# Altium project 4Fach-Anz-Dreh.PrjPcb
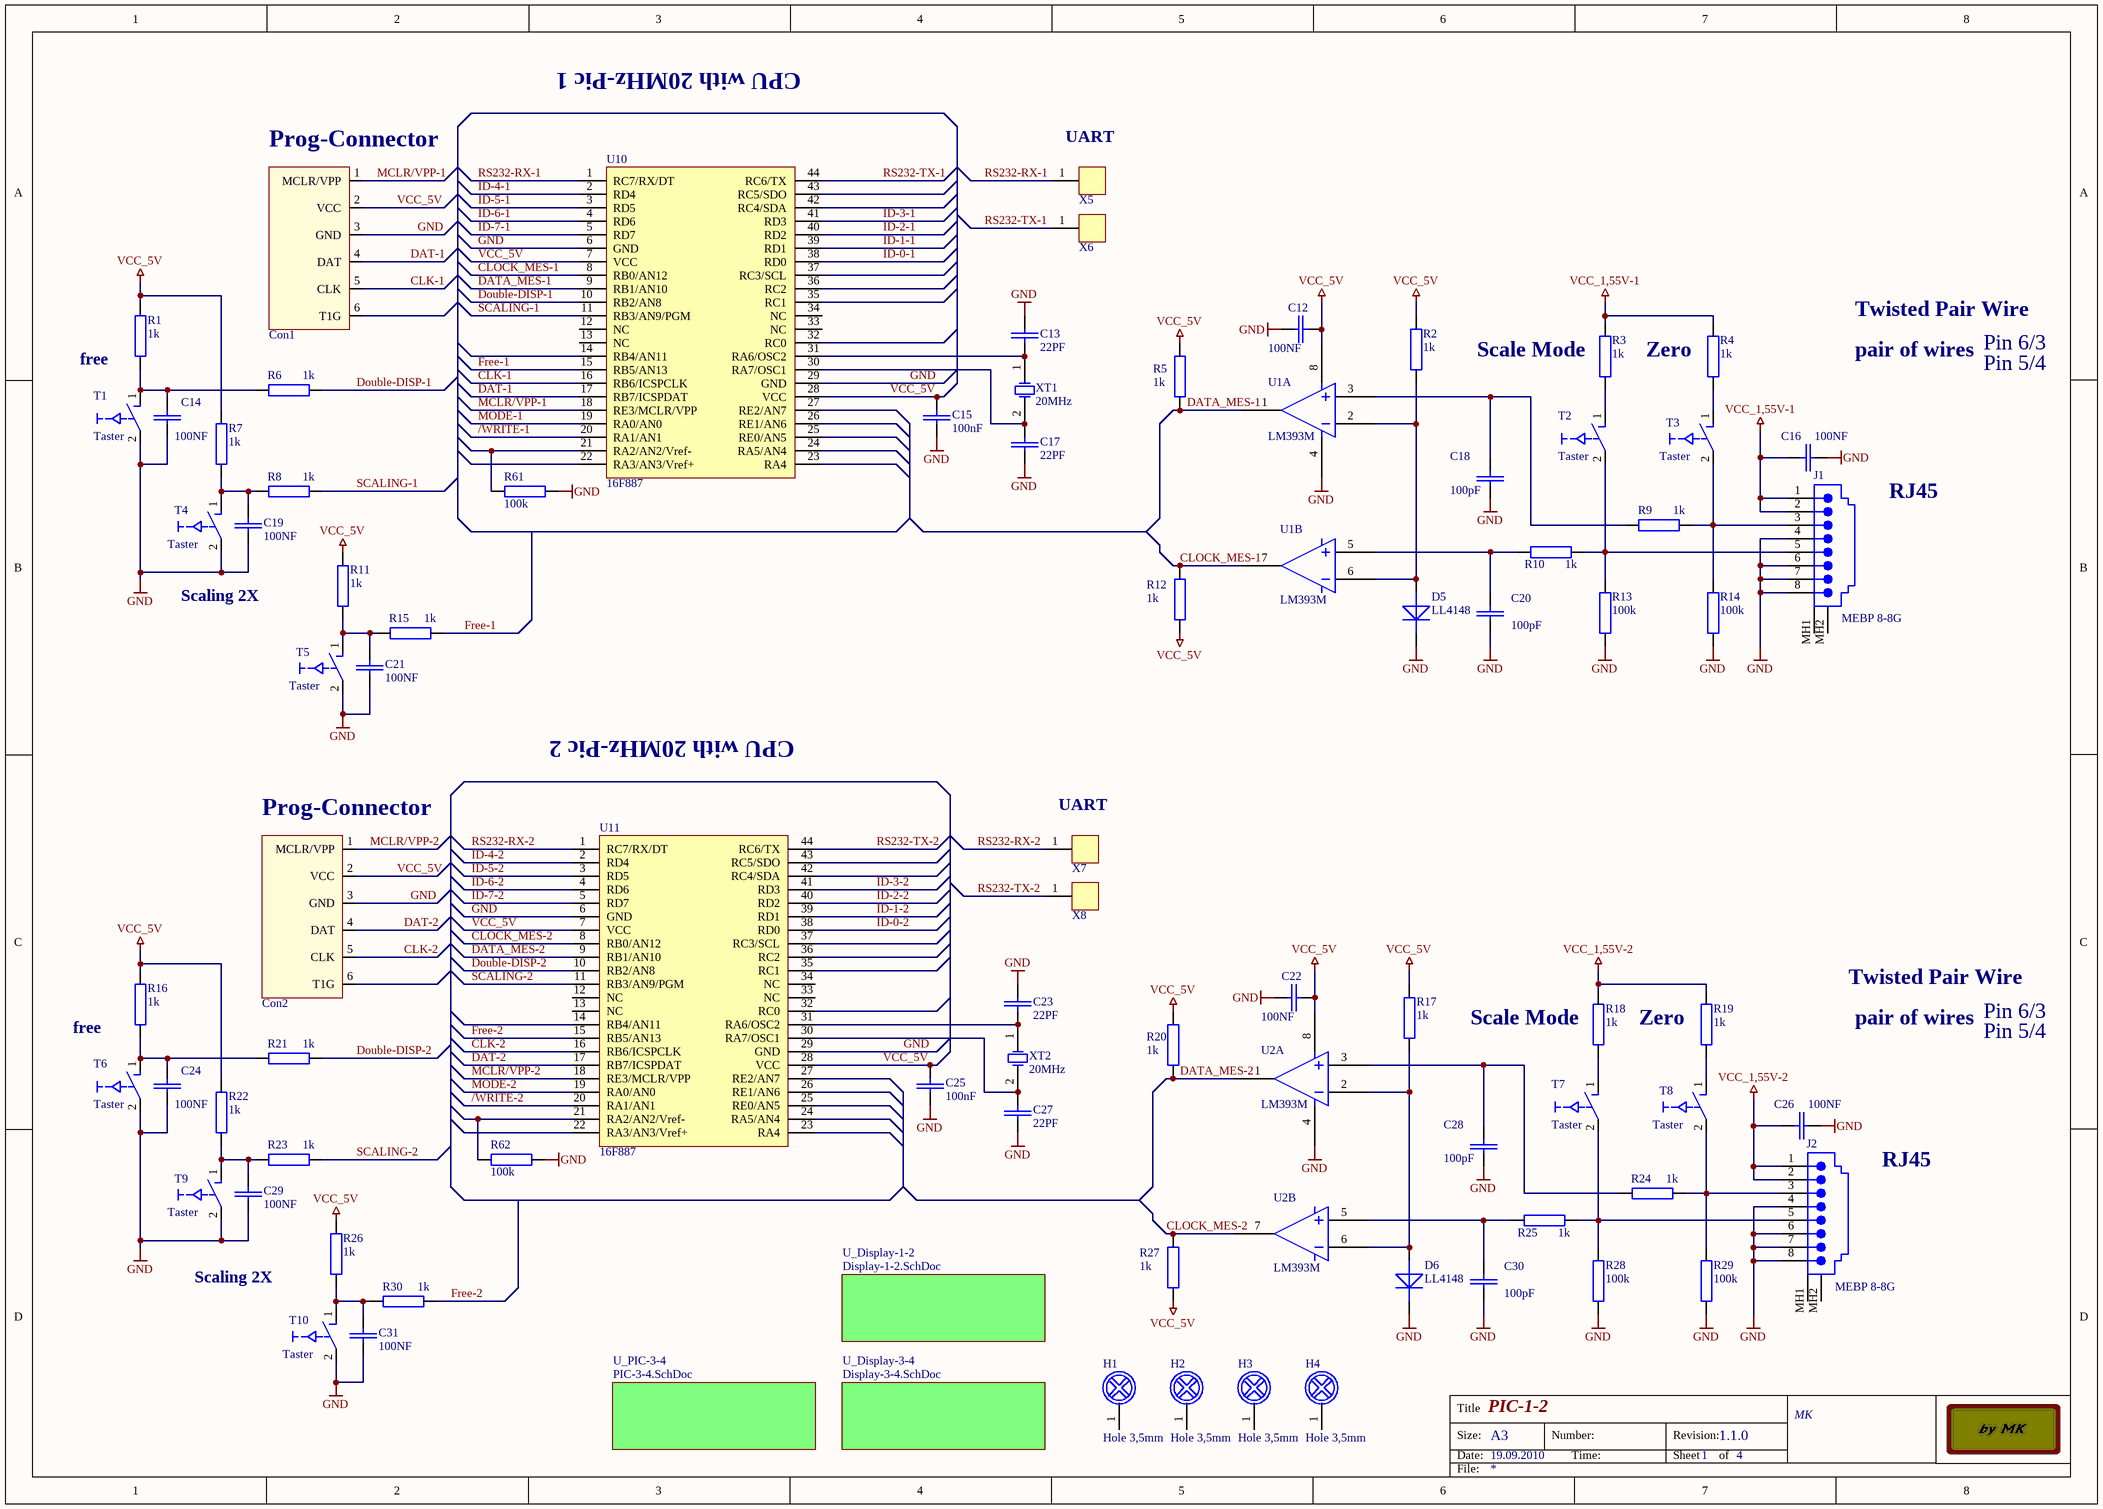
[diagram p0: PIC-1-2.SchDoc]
4 sheets, 204 parts. Net scope: global (net labels, ports and power ports of the same name join across sheets).
Board file: 4Fach-Anz-Dreh.PcbDoc
Sheets:
  PIC-1-2.SchDoc
    U_PIC-3-4 = PIC-3-4.SchDoc
    U_Display-1-2 = Display-1-2.SchDoc
    U_Display-3-4 = Display-3-4.SchDoc

## Sheet PIC-1-2.SchDoc: PIC-1-2
size A3; Organization: Altium Limited; Address1: MK; Revision: 1.1.0; SheetNumber: 1; SheetTotal: 4

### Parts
C12  100NF  [0805]
C13  22PF  [0805]
C14  100NF  [0805]
C15  100nF  [0805]
C16  100NF  [0805]
C17  22PF  [0805]
C18  100pF  [0805]
C19  100NF  [0805]
C20  100pF  [0805]
C21  100NF  [0805]
C22  100NF  [0805]
C23  22PF  [0805]
C24  100NF  [0805]
C25  100nF  [0805]
C26  100NF  [0805]
C27  22PF  [0805]
C28  100pF  [0805]
C29  100NF  [0805]
C30  100pF  [0805]
C31  100NF  [0805]
Con1  Con_6  [Con_6]  (value not drawn)
Con2  Con_6  [Con_6]  (value not drawn)
D5  LL4148  [MINIMELF]
D6  LL4148  [MINIMELF]
H1  Hole 3,5mm  [Hole 3,5mm]
H2  Hole 3,5mm  [Hole 3,5mm]
H3  Hole 3,5mm  [Hole 3,5mm]
H4  Hole 3,5mm  [Hole 3,5mm]
J1  MEBP 8-8G  [RJ45-JACK-MEBP 8-8G]
J2  MEBP 8-8G  [RJ45-JACK-MEBP 8-8G]
R1  1k  [0805]
R2  1k  [0805]
R3  1k  [0805]
R4  1k  [0805]
R5  1k  [0805]
R6  1k  [0805]
R7  1k  [0805]
R8  1k  [0805]
R9  1k  [0805]
R10  1k  [0805]
R11  1k  [0805]
R12  1k  [0805]
R13  100k  [0805]
R14  100k  [0805]
R15  1k  [0805]
R16  1k  [0805]
R17  1k  [0805]
R18  1k  [0805]
R19  1k  [0805]
R20  1k  [0805]
R21  1k  [0805]
R22  1k  [0805]
R23  1k  [0805]
R24  1k  [0805]
R25  1k  [0805]
R26  1k  [0805]
R27  1k  [0805]
R28  100k  [0805]
R29  100k  [0805]
R30  1k  [0805]
R61  100k  [0805]
R62  100k  [0805]
T1  Taster  [SIP2]
T2  Taster  [SIP2]
T3  Taster  [SIP2]
T4  Taster  [SIP2]
T5  Taster  [SIP2]
T6  Taster  [SIP2]
T7  Taster  [SIP2]
T8  Taster  [SIP2]
T9  Taster  [SIP2]
T10  Taster  [SIP2]
U1  LM393M  [SO-8]  (parts A,B of 2)
U2  LM393M  [SO-8]  (parts A,B of 2)
U10  16F887  [TQFP-44]
U11  16F887  [TQFP-44]
X5  Ground  [GND_PAD3]  (value not drawn)
X6  Ground  [GND_PAD3]  (value not drawn)
X7  Ground  [GND_PAD3]  (value not drawn)
X8  Ground  [GND_PAD3]  (value not drawn)
XT1  20MHz  [HC-49/U_ST]
XT2  20MHz  [HC-49/U_ST]

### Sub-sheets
U_Display-1-2 = Display-1-2.SchDoc: no entries
U_Display-3-4 = Display-3-4.SchDoc: no entries
U_PIC-3-4 = PIC-3-4.SchDoc: no entries

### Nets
GND: C12.2 C13.2 C14.2 C15.2 C16.2 C17.2 C18.2 C19.2 C20.2 C21.2 C22.2 C23.2 C24.2 C25.2 C26.2 C27.2 C28.2 C29.2 C30.2 C31.2 Con1.3(GND) Con2.3(GND) D5.K(CATHODE) D6.K(CATHODE) J1.4 J1.6 J1.7 J1.8 J2.4 J2.6 J2.7 J2.8 R13.2 R14.2 R28.2 R29.2 R61.2 R62.1 T1.2 T4.2 T5.2 T6.2 T9.2 T10.2 U1.4(V-) U2.4(V-) U10.6(GND) U10.29(GND) U11.6(GND) U11.29(GND)
VCC_1,55V-1: C16.1 J1.1 J1.2 R3.1 R4.1
VCC_1,55V-2: C26.1 J2.1 J2.2 R18.1 R19.1
VCC_5V: C12.1 C15.1 C22.1 C25.1 Con1.2(VCC) Con2.2(VCC) R1.1 R2.1 R5.2 R7.1 R11.1 R12.2 R16.1 R17.1 R20.2 R22.1 R26.1 R27.2 U1.8(V+) U2.8(V+) U10.7(VCC) U10.28(VCC) U11.7(VCC) U11.28(VCC)
/WRITE-1: U10.20(RA1/AN1)
/WRITE-2: U11.20(RA1/AN1)
CLK-1: Con1.5(CLK) U10.16(RB6/ICSPCLK)
CLK-2: Con2.5(CLK) U11.16(RB6/ICSPCLK)
CLOCK_MES-1: R12.1 U1.7 U10.8(RB0/AN12)
CLOCK_MES-2: R27.1 U2.7 U11.8(RB0/AN12)
DAT-1: Con1.4(DAT) U10.17(RB7/ICSPDAT)
DAT-2: Con2.4(DAT) U11.17(RB7/ICSPDAT)
DATA_MES-1: R5.1 U1.1 U10.9(RB1/AN10)
DATA_MES-2: R20.1 U2.1 U11.9(RB1/AN10)
Double-DISP-1: R6.2 U10.10(RB2/AN8)
Double-DISP-2: R21.2 U11.10(RB2/AN8)
Free-1: R15.2 U10.15(RB5/AN13)
Free-2: R30.2 U11.15(RB5/AN13)
ID-0-1: U10.38(RD0)
ID-0-2: U11.38(RD0)
ID-1-1: U10.39(RD1)
ID-1-2: U11.39(RD1)
ID-2-1: U10.40(RD2)
ID-2-2: U11.40(RD2)
ID-3-1: U10.41(RD3)
ID-3-2: U11.41(RD3)
ID-4-1: U10.2(RD4)
ID-4-2: U11.2(RD4)
ID-5-1: U10.3(RD5)
ID-5-2: U11.3(RD5)
ID-6-1: U10.4(RD6)
ID-6-2: U11.4(RD6)
ID-7-1: U10.5(RD7)
ID-7-2: U11.5(RD7)
MCLR/VPP-1: Con1.1(MCLR/VPP) U10.18(RE3/MCLR/VPP)
MCLR/VPP-2: Con2.1(MCLR/VPP) U11.18(RE3/MCLR/VPP)
MODE-1: U10.19(RA0/AN0)
MODE-2: U11.19(RA0/AN0)
RS232-RX-1: U10.1(RC7/RX/DT) X5.1
RS232-RX-2: U11.1(RC7/RX/DT) X7.1
RS232-TX-1: U10.44(RC6/TX) X6.1
RS232-TX-2: U11.44(RC6/TX) X8.1
SCALING-1: R8.2 U10.11(RB3/AN9/PGM)
SCALING-2: R23.2 U11.11(RB3/AN9/PGM)
NetC13_1: C13.1 U10.31(RA6/OSC2) XT1.1(OSC1)
NetC14_1: C14.1 R1.2 R6.1 T1.1
NetC17_1: C17.1 U10.30(RA7/OSC1) XT1.2(OSC2)
NetC18_1: C18.1 R9.1 U1.3
NetC19_1: C19.1 R7.2 R8.1 T4.1
NetC20_1: C20.1 R10.2 U1.5
NetC21_1: C21.1 R11.2 R15.1 T5.1
NetC23_1: C23.1 U11.31(RA6/OSC2) XT2.1(OSC1)
NetC24_1: C24.1 R16.2 R21.1 T6.1
NetC27_1: C27.1 U11.30(RA7/OSC1) XT2.2(OSC2)
NetC28_1: C28.1 R24.1 U2.3
NetC29_1: C29.1 R22.2 R23.1 T9.1
NetC30_1: C30.1 R25.2 U2.5
NetC31_1: C31.1 R26.2 R30.1 T10.1
NetD5_A: D5.A(ANODE) R2.2 U1.2 U1.6
NetD6_A: D6.A(ANODE) R17.2 U2.2 U2.6
NetJ1_3: J1.3 R9.2 R14.1 T3.2
NetJ1_5: J1.5 R10.1 R13.1 T2.2
NetJ2_3: J2.3 R24.2 R29.1 T8.2
NetJ2_5: J2.5 R25.1 R28.1 T7.2
NetR3_2: R3.2 T2.1
NetR4_2: R4.2 T3.1
NetR18_2: R18.2 T7.1
NetR19_2: R19.2 T8.1
NetR61_1: R61.1 U10.21(RA2/AN2/Vref-)
NetR62_2: R62.2 U11.21(RA2/AN2/Vref-)

Not connected (* = marked no-connect by the designer): Con1 6(T1G); Con2 6(T1G); H1 1; H2 1; H3 1; H4 1; J1 MH1(Shield) MH2(Shield); J2 MH1(Shield) MH2(Shield); U10 12(NC) 13(NC) 14(RB4/AN11) 22(RA3/AN3/Vref+) 23(RA4) 24(RA5/AN4) 25(RE0/AN5) 26(RE1/AN6) 27(RE2/AN7) 32(RC0) 33(NC) 34(NC) 35(RC1) 36(RC2) 37(RC3/SCL) 42(RC4/SDA) 43(RC5/SDO); U11 12(NC) 13(NC) 14(RB4/AN11) 22(RA3/AN3/Vref+) 23(RA4) 24(RA5/AN4) 25(RE0/AN5) 26(RE1/AN6) 27(RE2/AN7) 32(RC0) 33(NC) 34(NC) 35(RC1) 36(RC2) 37(RC3/SCL) 42(RC4/SDA) 43(RC5/SDO)

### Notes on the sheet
- CPU with 20MHz-Pic 1
- (near Con1) Prog-Connector
- (near X5) UART
- Twisted Pair Wire
- free
- (near R3) Scale Mode
- (near R4) Zero
- pair of wires
- Pin 6/3
- Pin 5/4
- RJ45
- Scaling 2X
- CPU with 20MHz-Pic 2
- (near Con2) Prog-Connector
- (near X7) UART
- (near R18) Scale Mode
- (near R19) Zero
- 19.09.2010

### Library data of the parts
C12 C14-C16 C19 C21 C22 C24-C26 C29 C31 = 100NF_0805: SMD Kondensator; Text Field1: 10%; Text Field3: 16V; Text Field5: 0603; Text Field6: Murata; Text Field7: RS;264-4422; Text Field8: 0,2132;SAP-NR.;220-7922
C13 C17 C23 C27 = 68PF_0805: SMD Kondensator; Text Field1: 5%; Text Field3: 50V; Text Field6: EPCOS;Farnell; Text Field7: 0,10;331-2884; Text Field8: 6507 3018
C18 C20 C28 C30 = 100PF_0805: Capacitor SMD; Part No.: 0157606; Tolerance: 10%; Class: passive; Voltage: 50V; Note: RoHS konf.; SAP No.: 6507 3077; Herst. Bezeichnung: MLCC NP0 0805 100pF 50V
D5 D6 = LL4148: Universal diode SMD; Manufacturer: VISHAY; Part No.: 9549986; Voltage: 75V; Current: 0,1A; SAP No.: 6506 2351; Class: passive; Note: RoHS konf.
J1 J2 = RJ45-JACK-MEBP 8-8G: Right Angle, Standard Profile, External Shield PCB Jack; Class: passive; Note: RoHS konf. / MEBP 8-8G; SubClass: Connector
R1-R12 R15-R27 R30 = 1k_0805: SMD Resistor; Part No.: 0234 1K; Power: 0,1W; Voltage: *V; SAP No.: 6507 4040; Tolerance: 1%; Class: passive; Note: RoHS Konf.
R13 R14 R28 R29 R61 R62 = 100K_0805: SMD Resistor; Part No.: 0234 100K; Power: 0,1W; Voltage: *V; SAP No.: 6507 4082; Tolerance: 1%; Class: passive; Note: RoHS Konf.
T1-T10 = TASTER_SCH
U1 U2 = LM393_SO-8: Dual Differential Comperator; Manufacturer: NATIONAL SEMICONDUCTOR; Part No.: 9487590; Class: active; Note: RoHS konf. /
U10 U11 = PIC-16F887: CPU
X5-X8 = GND_PAD3: Groundpad; Class: passive; SubClass: mechanic
XT1 XT2 = XTAL: Crystal Oscillator

## Sheet PIC-3-4.SchDoc: PIC-3-4
size A3; Organization: Altium Limited; Address1: MK; Revision: 1.1.0; SheetNumber: 2; SheetTotal: 4
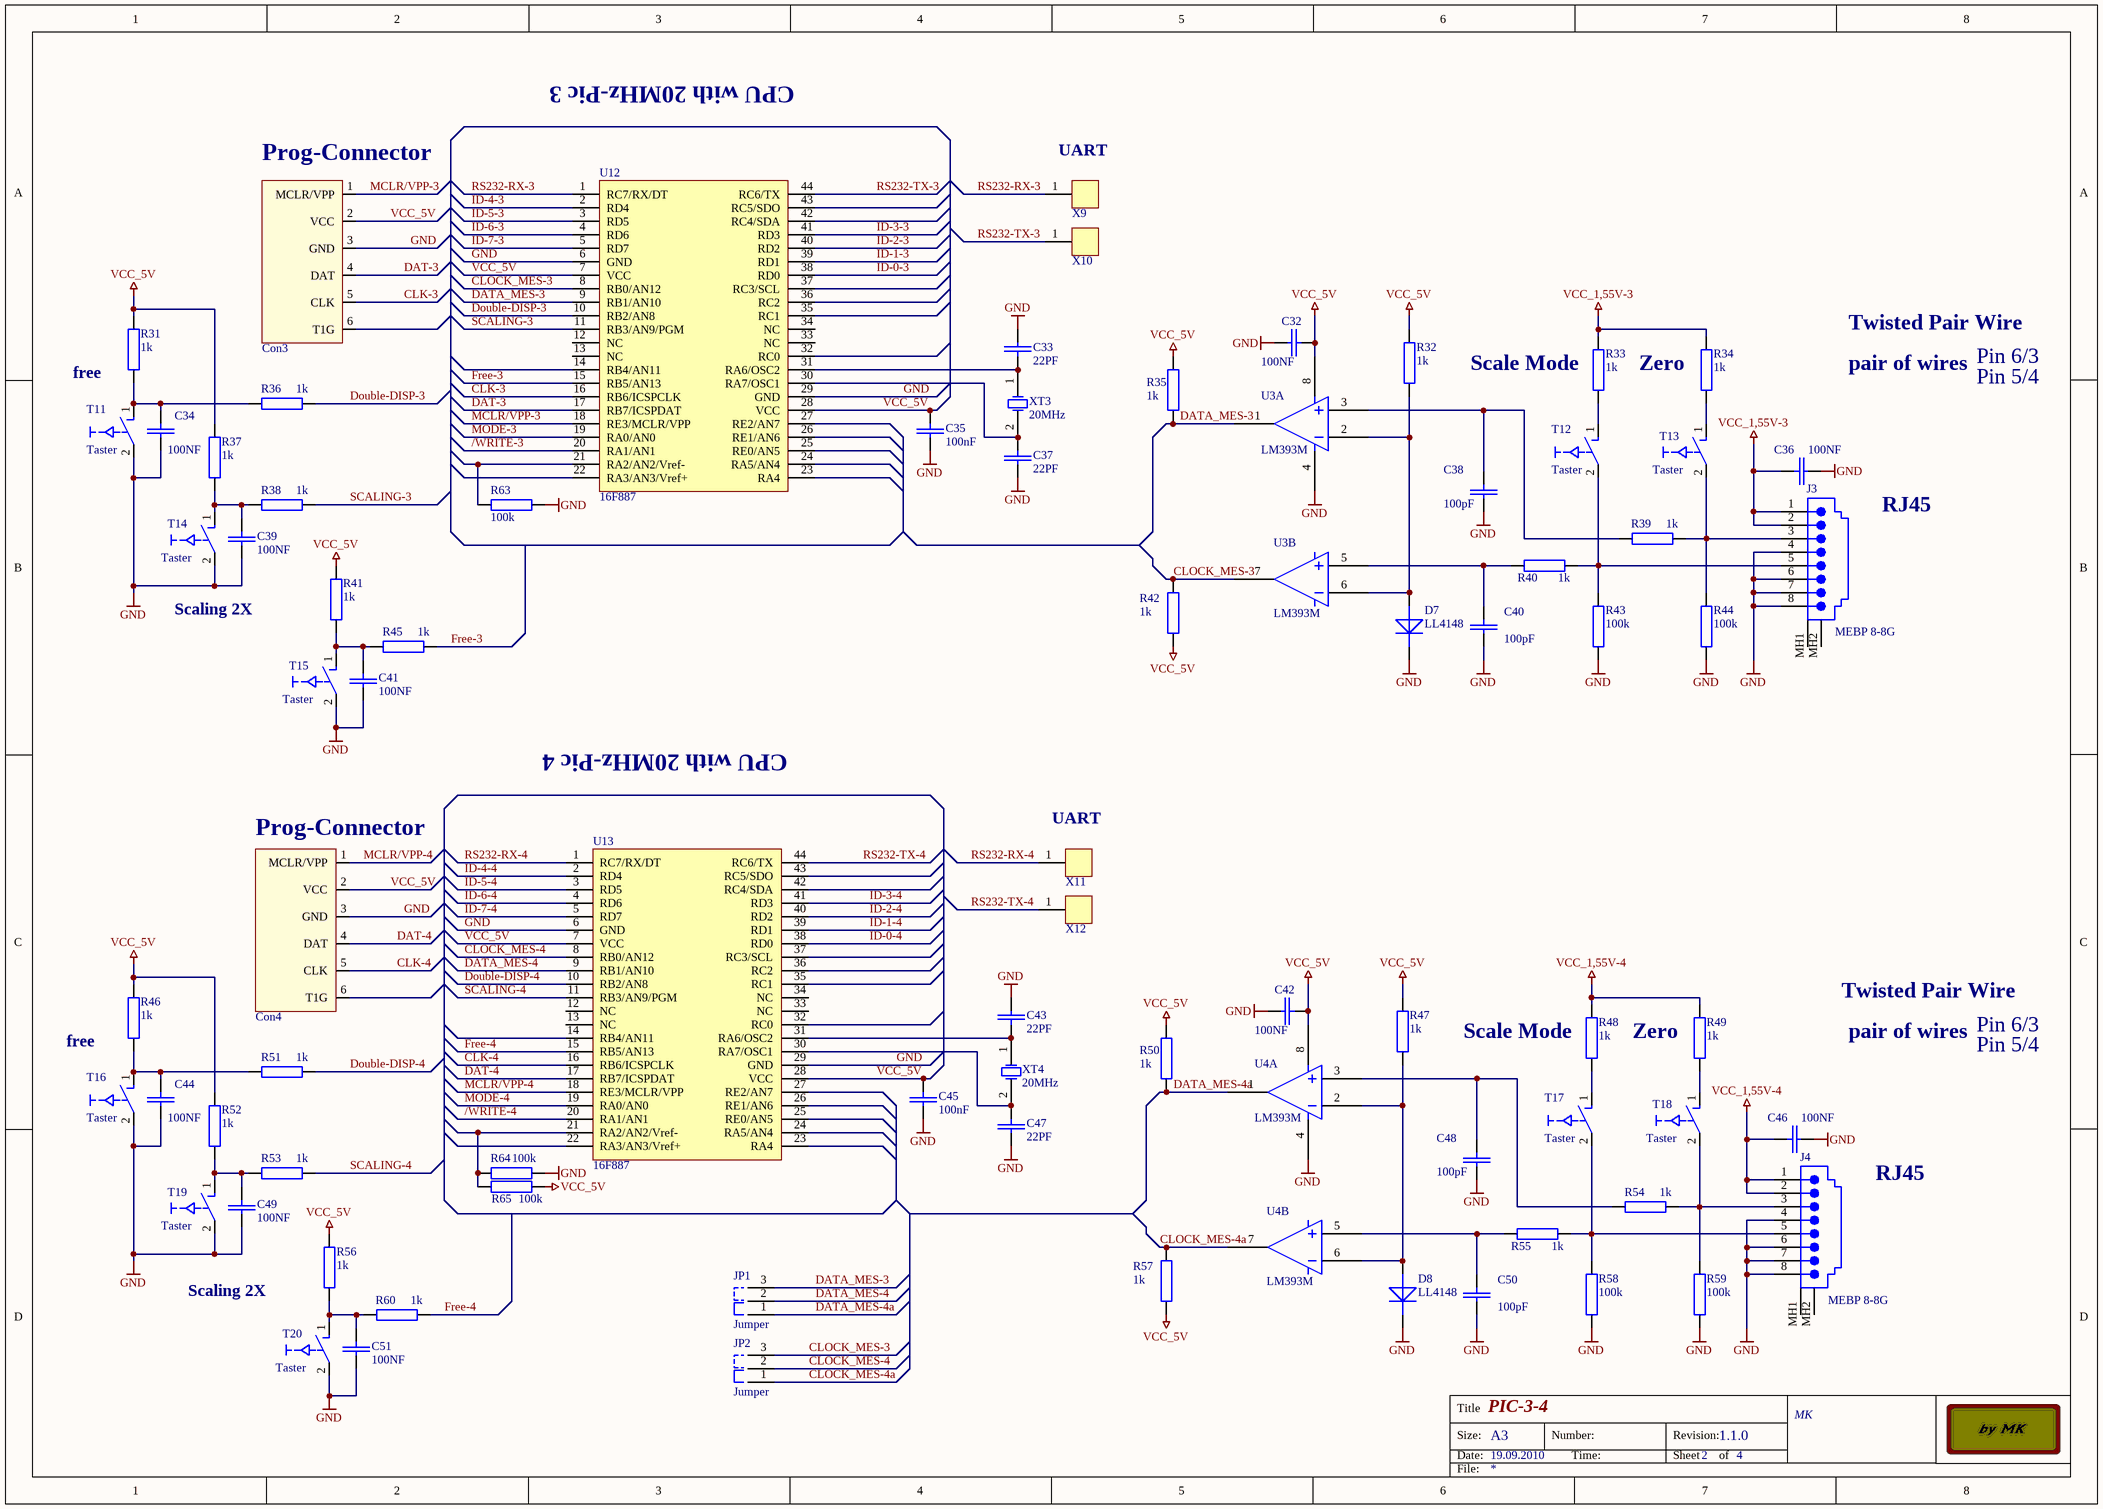
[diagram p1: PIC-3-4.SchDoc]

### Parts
C32  100NF  [0805]
C33  22PF  [0805]
C34  100NF  [0805]
C35  100nF  [0805]
C36  100NF  [0805]
C37  22PF  [0805]
C38  100pF  [0805]
C39  100NF  [0805]
C40  100pF  [0805]
C41  100NF  [0805]
C42  100NF  [0805]
C43  22PF  [0805]
C44  100NF  [0805]
C45  100nF  [0805]
C46  100NF  [0805]
C47  22PF  [0805]
C48  100pF  [0805]
C49  100NF  [0805]
C50  100pF  [0805]
C51  100NF  [0805]
Con3  Con_6  [Con_6]  (value not drawn)
Con4  Con_6  [Con_6]  (value not drawn)
D7  LL4148  [MINIMELF]
D8  LL4148  [MINIMELF]
J3  MEBP 8-8G  [RJ45-JACK-MEBP 8-8G]
J4  MEBP 8-8G  [RJ45-JACK-MEBP 8-8G]
JP1  Jumper  [SIP3]
JP2  Jumper  [SIP3]
R31  1k  [0805]
R32  1k  [0805]
R33  1k  [0805]
R34  1k  [0805]
R35  1k  [0805]
R36  1k  [0805]
R37  1k  [0805]
R38  1k  [0805]
R39  1k  [0805]
R40  1k  [0805]
R41  1k  [0805]
R42  1k  [0805]
R43  100k  [0805]
R44  100k  [0805]
R45  1k  [0805]
R46  1k  [0805]
R47  1k  [0805]
R48  1k  [0805]
R49  1k  [0805]
R50  1k  [0805]
R51  1k  [0805]
R52  1k  [0805]
R53  1k  [0805]
R54  1k  [0805]
R55  1k  [0805]
R56  1k  [0805]
R57  1k  [0805]
R58  100k  [0805]
R59  100k  [0805]
R60  1k  [0805]
R63  100k  [0805]
R64  100k  [0805]
R65  100k  [0805]
T11  Taster  [SIP2]
T12  Taster  [SIP2]
T13  Taster  [SIP2]
T14  Taster  [SIP2]
T15  Taster  [SIP2]
T16  Taster  [SIP2]
T17  Taster  [SIP2]
T18  Taster  [SIP2]
T19  Taster  [SIP2]
T20  Taster  [SIP2]
U3  LM393M  [SO-8]  (parts A,B of 2)
U4  LM393M  [SO-8]  (parts A,B of 2)
U12  16F887  [TQFP-44]
U13  16F887  [TQFP-44]
X9  Ground  [GND_PAD3]  (value not drawn)
X10  Ground  [GND_PAD3]  (value not drawn)
X11  Ground  [GND_PAD3]  (value not drawn)
X12  Ground  [GND_PAD3]  (value not drawn)
XT3  20MHz  [HC-49/U_ST]
XT4  20MHz  [HC-49/U_ST]

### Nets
GND: C32.2 C33.2 C34.2 C35.2 C36.2 C37.2 C38.2 C39.2 C40.2 C41.2 C42.2 C43.2 C44.2 C45.2 C46.2 C47.2 C48.2 C49.2 C50.2 C51.2 Con3.3(GND) Con4.3(GND) D7.K(CATHODE) D8.K(CATHODE) J3.4 J3.6 J3.7 J3.8 J4.4 J4.6 J4.7 J4.8 R43.2 R44.2 R58.2 R59.2 R63.1 R64.2 T11.2 T14.2 T15.2 T16.2 T19.2 T20.2 U3.4(V-) U4.4(V-) U12.6(GND) U12.29(GND) U13.6(GND) U13.29(GND)
VCC_1,55V-3: C36.1 J3.1 J3.2 R33.1 R34.1
VCC_1,55V-4: C46.1 J4.1 J4.2 R48.1 R49.1
VCC_5V: C32.1 C35.1 C42.1 C45.1 Con3.2(VCC) Con4.2(VCC) R31.1 R32.1 R35.2 R37.1 R41.1 R42.2 R46.1 R47.1 R50.2 R52.1 R56.1 R57.2 R65.2 U3.8(V+) U4.8(V+) U12.7(VCC) U12.28(VCC) U13.7(VCC) U13.28(VCC)
/WRITE-3: U12.20(RA1/AN1)
/WRITE-4: U13.20(RA1/AN1)
CLK-3: Con3.5(CLK) U12.16(RB6/ICSPCLK)
CLK-4: Con4.5(CLK) U13.16(RB6/ICSPCLK)
CLOCK_MES-3: JP2.3 R42.1 U3.7 U12.8(RB0/AN12)
CLOCK_MES-4: JP2.2 U13.8(RB0/AN12)
CLOCK_MES-4a: JP2.1 R57.1 U4.7
DAT-3: Con3.4(DAT) U12.17(RB7/ICSPDAT)
DAT-4: Con4.4(DAT) U13.17(RB7/ICSPDAT)
DATA_MES-3: JP1.3 R35.1 U3.1 U12.9(RB1/AN10)
DATA_MES-4: JP1.2 U13.9(RB1/AN10)
DATA_MES-4a: JP1.1 R50.1 U4.1
Double-DISP-3: R36.2 U12.10(RB2/AN8)
Double-DISP-4: R51.2 U13.10(RB2/AN8)
Free-3: R45.2 U12.15(RB5/AN13)
Free-4: R60.2 U13.15(RB5/AN13)
ID-0-3: U12.38(RD0)
ID-0-4: U13.38(RD0)
ID-1-3: U12.39(RD1)
ID-1-4: U13.39(RD1)
ID-2-3: U12.40(RD2)
ID-2-4: U13.40(RD2)
ID-3-3: U12.41(RD3)
ID-3-4: U13.41(RD3)
ID-4-3: U12.2(RD4)
ID-4-4: U13.2(RD4)
ID-5-3: U12.3(RD5)
ID-5-4: U13.3(RD5)
ID-6-3: U12.4(RD6)
ID-6-4: U13.4(RD6)
ID-7-3: U12.5(RD7)
ID-7-4: U13.5(RD7)
MCLR/VPP-3: Con3.1(MCLR/VPP) U12.18(RE3/MCLR/VPP)
MCLR/VPP-4: Con4.1(MCLR/VPP) U13.18(RE3/MCLR/VPP)
MODE-3: U12.19(RA0/AN0)
MODE-4: U13.19(RA0/AN0)
RS232-RX-3: U12.1(RC7/RX/DT) X9.1
RS232-RX-4: U13.1(RC7/RX/DT) X11.1
RS232-TX-3: U12.44(RC6/TX) X10.1
RS232-TX-4: U13.44(RC6/TX) X12.1
SCALING-3: R38.2 U12.11(RB3/AN9/PGM)
SCALING-4: R53.2 U13.11(RB3/AN9/PGM)
NetC33_1: C33.1 U12.31(RA6/OSC2) XT3.1(OSC1)
NetC34_1: C34.1 R31.2 R36.1 T11.1
NetC37_1: C37.1 U12.30(RA7/OSC1) XT3.2(OSC2)
NetC38_1: C38.1 R39.1 U3.3
NetC39_1: C39.1 R37.2 R38.1 T14.1
NetC40_1: C40.1 R40.2 U3.5
NetC41_1: C41.1 R41.2 R45.1 T15.1
NetC43_1: C43.1 U13.31(RA6/OSC2) XT4.1(OSC1)
NetC44_1: C44.1 R46.2 R51.1 T16.1
NetC47_1: C47.1 U13.30(RA7/OSC1) XT4.2(OSC2)
NetC48_1: C48.1 R54.1 U4.3
NetC49_1: C49.1 R52.2 R53.1 T19.1
NetC50_1: C50.1 R55.2 U4.5
NetC51_1: C51.1 R56.2 R60.1 T20.1
NetD7_A: D7.A(ANODE) R32.2 U3.2 U3.6
NetD8_A: D8.A(ANODE) R47.2 U4.2 U4.6
NetJ3_3: J3.3 R39.2 R44.1 T13.2
NetJ3_5: J3.5 R40.1 R43.1 T12.2
NetJ4_3: J4.3 R54.2 R59.1 T18.2
NetJ4_5: J4.5 R55.1 R58.1 T17.2
NetR33_2: R33.2 T12.1
NetR34_2: R34.2 T13.1
NetR48_2: R48.2 T17.1
NetR49_2: R49.2 T18.1
NetR63_2: R63.2 U12.21(RA2/AN2/Vref-)
NetR64_1: R64.1 R65.1 U13.21(RA2/AN2/Vref-)

Not connected (* = marked no-connect by the designer): Con3 6(T1G); Con4 6(T1G); J3 MH1(Shield) MH2(Shield); J4 MH1(Shield) MH2(Shield); U12 12(NC) 13(NC) 14(RB4/AN11) 22(RA3/AN3/Vref+) 23(RA4) 24(RA5/AN4) 25(RE0/AN5) 26(RE1/AN6) 27(RE2/AN7) 32(RC0) 33(NC) 34(NC) 35(RC1) 36(RC2) 37(RC3/SCL) 42(RC4/SDA) 43(RC5/SDO); U13 12(NC) 13(NC) 14(RB4/AN11) 22(RA3/AN3/Vref+) 23(RA4) 24(RA5/AN4) 25(RE0/AN5) 26(RE1/AN6) 27(RE2/AN7) 32(RC0) 33(NC) 34(NC) 35(RC1) 36(RC2) 37(RC3/SCL) 42(RC4/SDA) 43(RC5/SDO)

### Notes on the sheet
- CPU with 20MHz-Pic 3
- (near Con3) Prog-Connector
- (near X9) UART
- free
- (near R33) Scale Mode
- (near R34) Zero
- Twisted Pair Wire
- pair of wires
- Pin 6/3
- Pin 5/4
- RJ45
- Scaling 2X
- CPU with 20MHz-Pic 4
- (near Con4) Prog-Connector
- (near X11) UART
- (near R48) Scale Mode
- (near R49) Zero
- 19.09.2010

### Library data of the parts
C32 C34-C36 C39 C41 C42 C44-C46 C49 C51 = 100NF_0805: as C12 on sheet PIC-1-2
C33 C37 C43 C47 = 68PF_0805: as C13 on sheet PIC-1-2
C38 C40 C48 C50 = 100PF_0805: as C18 on sheet PIC-1-2
D7 D8 = LL4148: as D5 on sheet PIC-1-2
J3 J4 = RJ45-JACK-MEBP 8-8G: as J1 on sheet PIC-1-2
JP1 JP2 = JUMPER3: Lötaugen; Class: passive; SubClass: Connector
R31-R42 R45-R57 R60 = 1k_0805: as R1 on sheet PIC-1-2
R43 R44 R58 R59 R63-R65 = 100K_0805: as R13 on sheet PIC-1-2
T11-T20 = TASTER_SCH
U3 U4 = LM393_SO-8: as U1 on sheet PIC-1-2
U12 U13 = PIC-16F887: CPU
X9-X12 = GND_PAD3: as X5 on sheet PIC-1-2
XT3 XT4 = XTAL: Crystal Oscillator

## Sheet Display-1-2.SchDoc: Display-1-2
size A3; Organization: Altium Limited; Address1: MK; Revision: 1.1.0; SheetNumber: 3; SheetTotal: 4
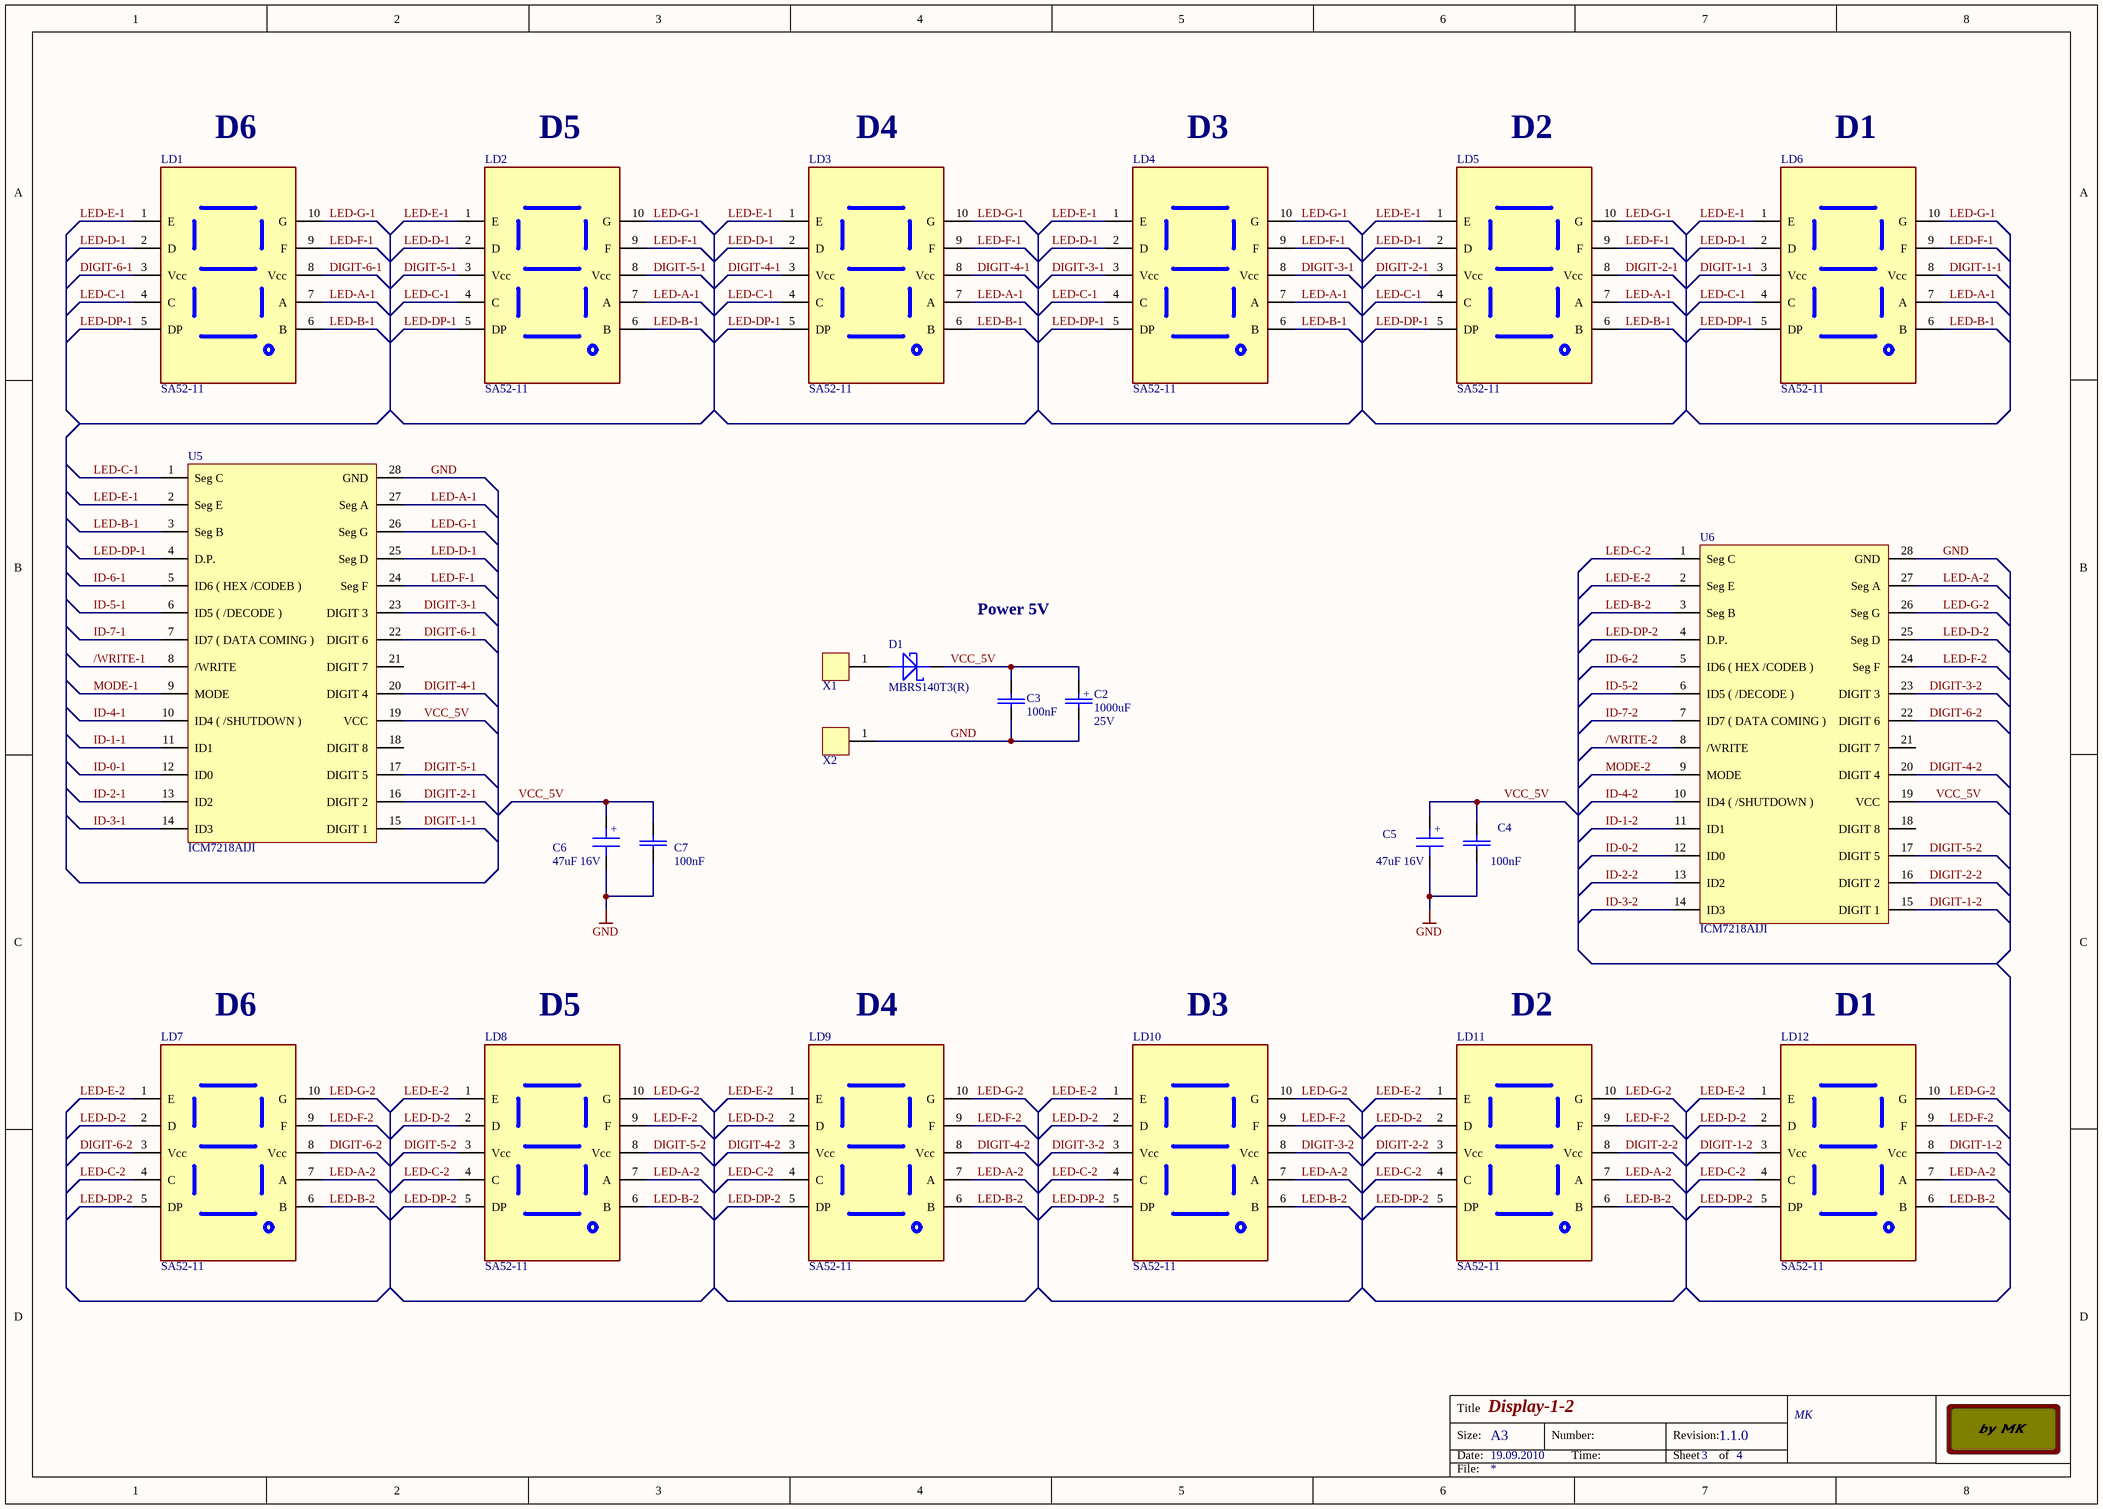
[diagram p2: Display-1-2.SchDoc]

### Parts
C2  1000uF  TechSpannung: 25V  [ELK_RM050_10x12.5]
C3  100nF  [0805]
C4  100nF  [0805]
C5  47uF 16V  [Bauform_C]
C6  47uF 16V  [Bauform_C]
C7  100nF  [0805]
D1  MBRS140T3(R)  [SMB]
LD1  SA52-11  [SA52-11]
LD2  SA52-11  [SA52-11]
LD3  SA52-11  [SA52-11]
LD4  SA52-11  [SA52-11]
LD5  SA52-11  [SA52-11]
LD6  SA52-11  [SA52-11]
LD7  SA52-11  [SA52-11]
LD8  SA52-11  [SA52-11]
LD9  SA52-11  [SA52-11]
LD10  SA52-11  [SA52-11]
LD11  SA52-11  [SA52-11]
LD12  SA52-11  [SA52-11]
U5  ICM7218AIJI  [ICM7218AIJM]
U6  ICM7218AIJI  [ICM7218AIJM]
X1  Ground  [GND_PAD3]  (value not drawn)
X2  Ground  [GND_PAD3]  (value not drawn)

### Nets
GND: C2.2 C3.2 C4.2 C5.2 C6.2 C7.2 U5.28(GND) U6.28(GND) X2.1
VCC_5V: C2.1 C3.1 C4.1 C5.1 C6.1 C7.1 D1.K(CATHODE) U5.19(VCC) U6.19(VCC)
/WRITE-1: U5.8(/WRITE)
/WRITE-2: U6.8(/WRITE)
DIGIT-1-1: LD6.3(Vcc) LD6.8(Vcc) U5.15(DIGIT_1)
DIGIT-1-2: LD12.3(Vcc) LD12.8(Vcc) U6.15(DIGIT_1)
DIGIT-2-1: LD5.3(Vcc) LD5.8(Vcc) U5.16(DIGIT_2)
DIGIT-2-2: LD11.3(Vcc) LD11.8(Vcc) U6.16(DIGIT_2)
DIGIT-3-1: LD4.3(Vcc) LD4.8(Vcc) U5.23(DIGIT_3)
DIGIT-3-2: LD10.3(Vcc) LD10.8(Vcc) U6.23(DIGIT_3)
DIGIT-4-1: LD3.3(Vcc) LD3.8(Vcc) U5.20(DIGIT_4)
DIGIT-4-2: LD9.3(Vcc) LD9.8(Vcc) U6.20(DIGIT_4)
DIGIT-5-1: LD2.3(Vcc) LD2.8(Vcc) U5.17(DIGIT_5)
DIGIT-5-2: LD8.3(Vcc) LD8.8(Vcc) U6.17(DIGIT_5)
DIGIT-6-1: LD1.3(Vcc) LD1.8(Vcc) U5.22(DIGIT_6)
DIGIT-6-2: LD7.3(Vcc) LD7.8(Vcc) U6.22(DIGIT_6)
ID-0-1: U5.12(ID0)
ID-0-2: U6.12(ID0)
ID-1-1: U5.11(ID1)
ID-1-2: U6.11(ID1)
ID-2-1: U5.13(ID2)
ID-2-2: U6.13(ID2)
ID-3-1: U5.14(ID3)
ID-3-2: U6.14(ID3)
ID-4-1: U5.10(ID4_(_/SHUTDOWN_))
ID-4-2: U6.10(ID4_(_/SHUTDOWN_))
ID-5-1: U5.6(ID5_(_/DECODE_))
ID-5-2: U6.6(ID5_(_/DECODE_))
ID-6-1: U5.5(ID6_(_HEX_/CODEB_))
ID-6-2: U6.5(ID6_(_HEX_/CODEB_))
ID-7-1: U5.7(ID7_(_DATA_COMING_))
ID-7-2: U6.7(ID7_(_DATA_COMING_))
LED-A-1: LD1.7(A) LD2.7(A) LD3.7(A) LD4.7(A) LD5.7(A) LD6.7(A) U5.27(Seg_A)
LED-A-2: LD7.7(A) LD8.7(A) LD9.7(A) LD10.7(A) LD11.7(A) LD12.7(A) U6.27(Seg_A)
LED-B-1: LD1.6(B) LD2.6(B) LD3.6(B) LD4.6(B) LD5.6(B) LD6.6(B) U5.3(Seg_B)
LED-B-2: LD7.6(B) LD8.6(B) LD9.6(B) LD10.6(B) LD11.6(B) LD12.6(B) U6.3(Seg_B)
LED-C-1: LD1.4(C) LD2.4(C) LD3.4(C) LD4.4(C) LD5.4(C) LD6.4(C) U5.1(Seg_C)
LED-C-2: LD7.4(C) LD8.4(C) LD9.4(C) LD10.4(C) LD11.4(C) LD12.4(C) U6.1(Seg_C)
LED-D-1: LD1.2(D) LD2.2(D) LD3.2(D) LD4.2(D) LD5.2(D) LD6.2(D) U5.25(Seg_D)
LED-D-2: LD7.2(D) LD8.2(D) LD9.2(D) LD10.2(D) LD11.2(D) LD12.2(D) U6.25(Seg_D)
LED-DP-1: LD1.5(DP) LD2.5(DP) LD3.5(DP) LD4.5(DP) LD5.5(DP) LD6.5(DP) U5.4(D.P.)
LED-DP-2: LD7.5(DP) LD8.5(DP) LD9.5(DP) LD10.5(DP) LD11.5(DP) LD12.5(DP) U6.4(D.P.)
LED-E-1: LD1.1(E) LD2.1(E) LD3.1(E) LD4.1(E) LD5.1(E) LD6.1(E) U5.2(Seg_E)
LED-E-2: LD7.1(E) LD8.1(E) LD9.1(E) LD10.1(E) LD11.1(E) LD12.1(E) U6.2(Seg_E)
LED-F-1: LD1.9(F) LD2.9(F) LD3.9(F) LD4.9(F) LD5.9(F) LD6.9(F) U5.24(Seg_F)
LED-F-2: LD7.9(F) LD8.9(F) LD9.9(F) LD10.9(F) LD11.9(F) LD12.9(F) U6.24(Seg_F)
LED-G-1: LD1.10(G) LD2.10(G) LD3.10(G) LD4.10(G) LD5.10(G) LD6.10(G) U5.26(Seg_G)
LED-G-2: LD7.10(G) LD8.10(G) LD9.10(G) LD10.10(G) LD11.10(G) LD12.10(G) U6.26(Seg_G)
MODE-1: U5.9(MODE)
MODE-2: U6.9(MODE)
NetD1_A: D1.A(ANODE) X1.1

Not connected (* = marked no-connect by the designer): U5 18(DIGIT_8) 21(DIGIT_7); U6 18(DIGIT_8) 21(DIGIT_7)

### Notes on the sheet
- D6
- D5
- D4
- D3
- D2
- D1
- Power 5V
- 19.09.2010

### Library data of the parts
C2 = 1000UF_RM5_25V: Capacitor Aluminum Electrolytic, 1000UF, 25V, 20%, 105°C, Low impedance; Manufacturer: RUBYCON; Part No.: 1144624; Class: passive; Note: RoHS konf. / High Ripple Current; Herst. Bezeichnung: 25YXF1000M12.5X20
C3 C4 C7 = 100NF_0805: as C12 on sheet PIC-1-2
C5 C6 = TR3 Tantal 47uF 16V: Tantal 47uF 16V
D1 = MBRS140T3(R)_SMB: Schottkydiode _SMD; Manufacturer: ON; Part No.: MBRS 140 SMD;MBRS140T3G; 9557237; Voltage: 40V; Current: 1A; Class: passive; Note: RoHS konf.; Herst. Bezeichnung: MBRS140T3G
LD1-LD12 = SA52-11: 7-Segment-Anzeige 13mm
X1 X2 = GND_PAD3: as X5 on sheet PIC-1-2

## Sheet Display-3-4.SchDoc: Display-3-4
size A3; Organization: Altium Limited; Address1: MK; Revision: 1.1.0; SheetNumber: 4; SheetTotal: 4
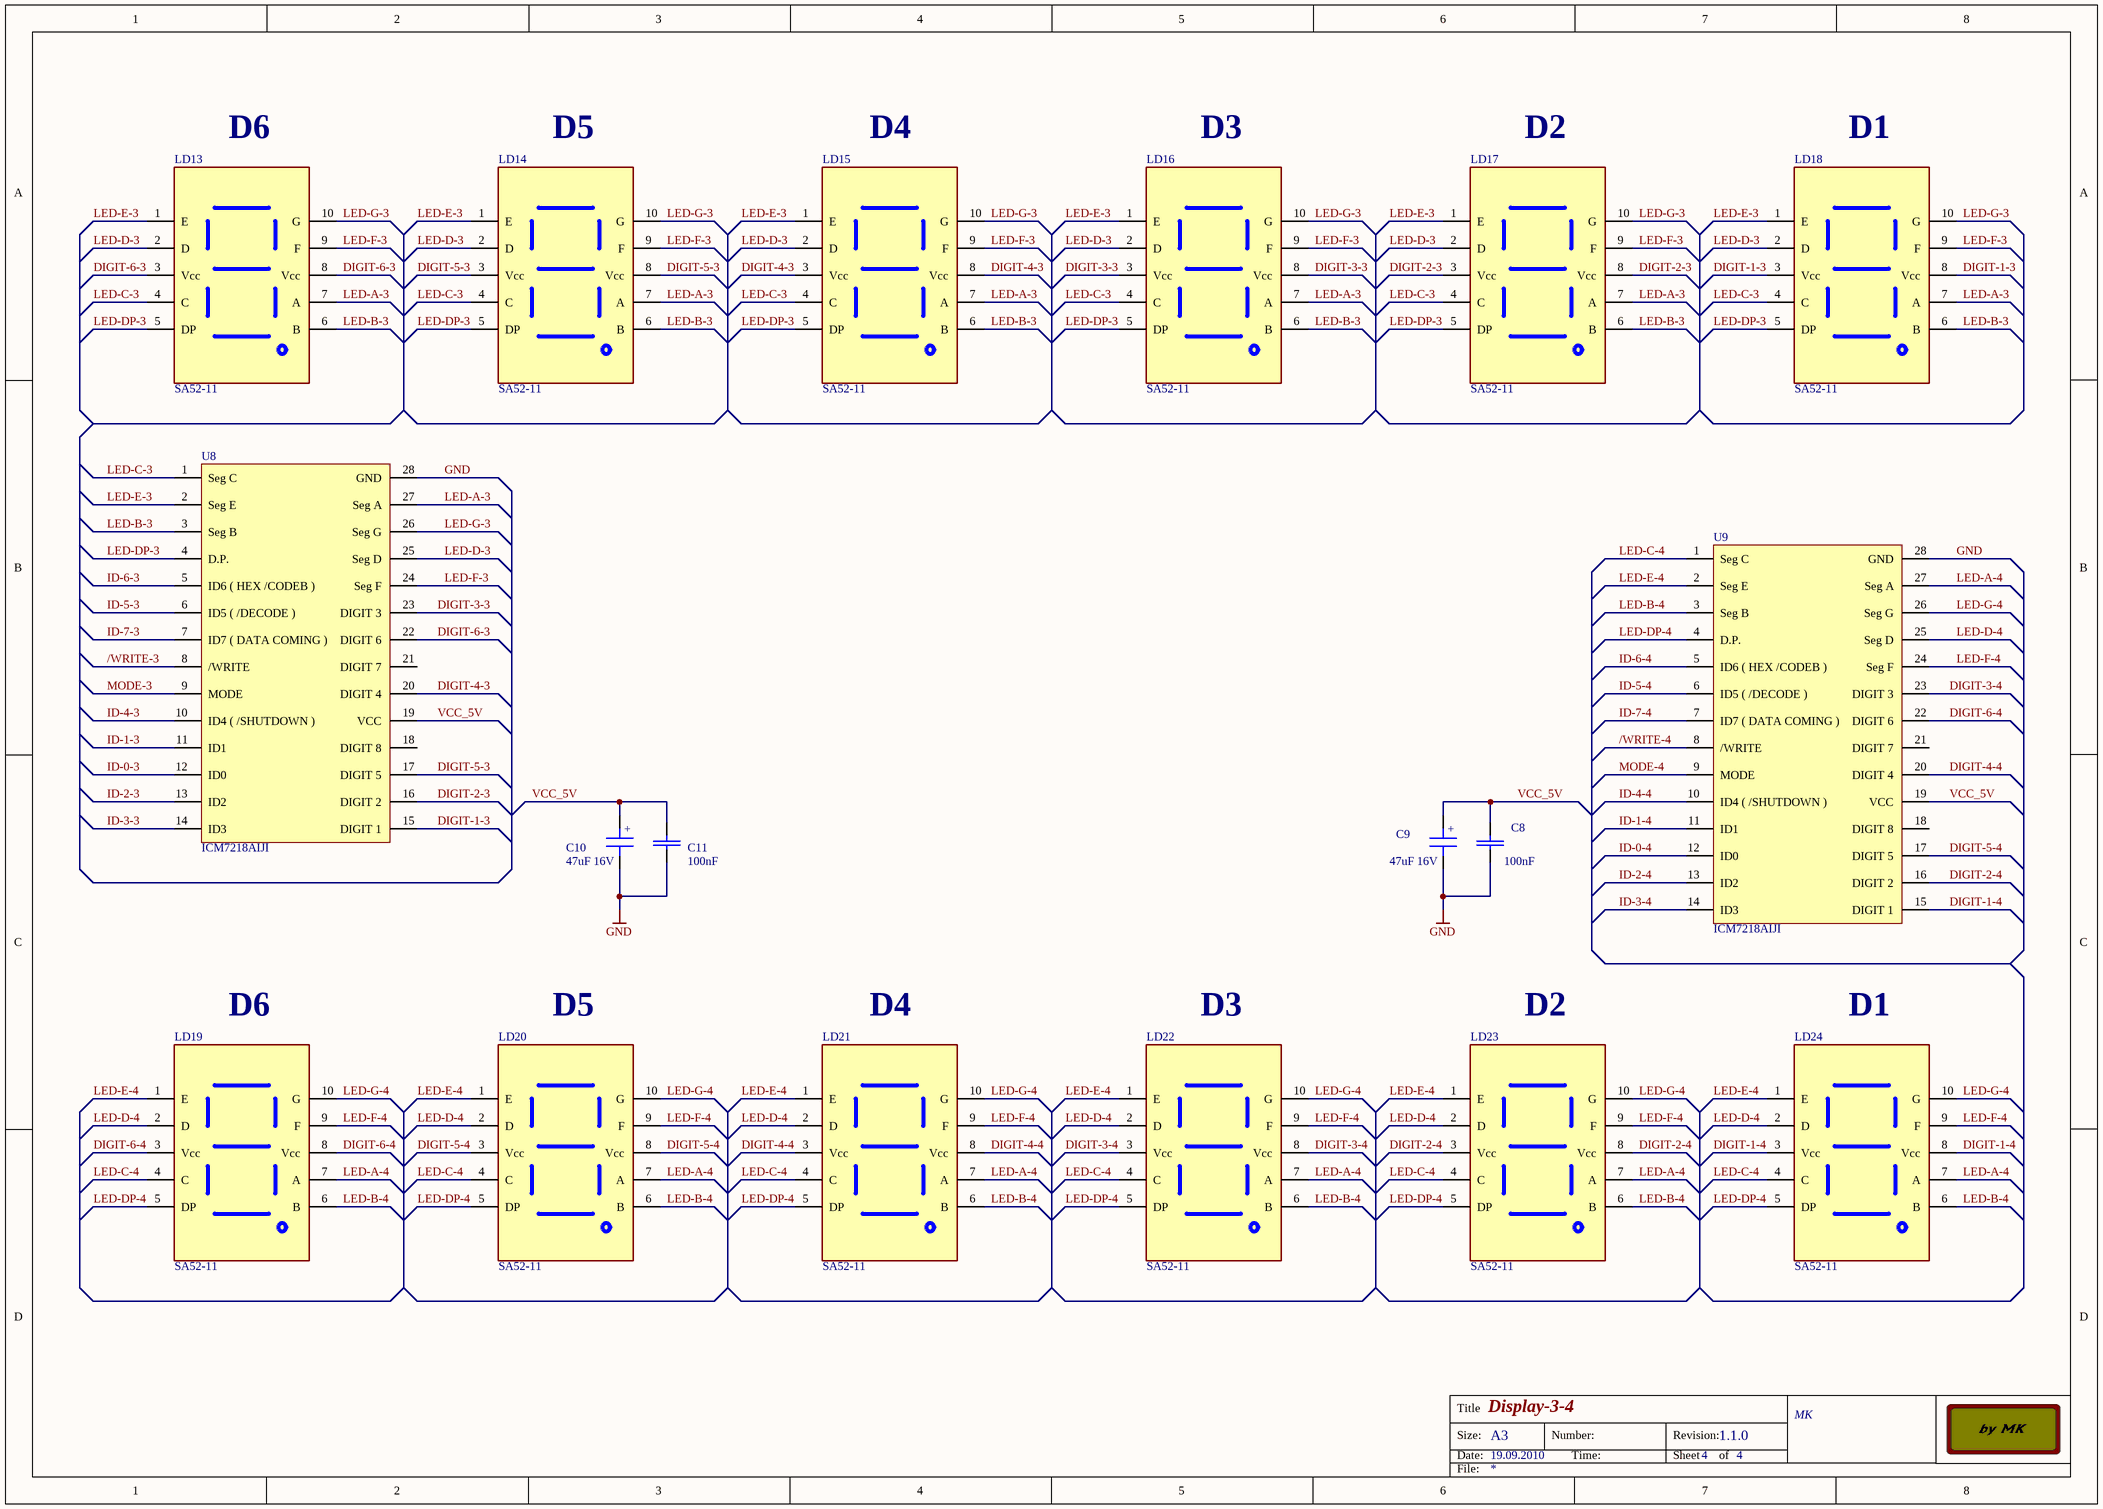
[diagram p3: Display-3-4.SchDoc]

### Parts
C8  100nF  [0805]
C9  47uF 16V  [Bauform_C]
C10  47uF 16V  [Bauform_C]
C11  100nF  [0805]
LD13  SA52-11  [SA52-11]
LD14  SA52-11  [SA52-11]
LD15  SA52-11  [SA52-11]
LD16  SA52-11  [SA52-11]
LD17  SA52-11  [SA52-11]
LD18  SA52-11  [SA52-11]
LD19  SA52-11  [SA52-11]
LD20  SA52-11  [SA52-11]
LD21  SA52-11  [SA52-11]
LD22  SA52-11  [SA52-11]
LD23  SA52-11  [SA52-11]
LD24  SA52-11  [SA52-11]
U8  ICM7218AIJI  [ICM7218AIJM]
U9  ICM7218AIJI  [ICM7218AIJM]

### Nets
GND: C8.2 C9.2 C10.2 C11.2 U8.28(GND) U9.28(GND)
VCC_5V: C8.1 C9.1 C10.1 C11.1 U8.19(VCC) U9.19(VCC)
/WRITE-3: U8.8(/WRITE)
/WRITE-4: U9.8(/WRITE)
DIGIT-1-3: LD18.3(Vcc) LD18.8(Vcc) U8.15(DIGIT_1)
DIGIT-1-4: LD24.3(Vcc) LD24.8(Vcc) U9.15(DIGIT_1)
DIGIT-2-3: LD17.3(Vcc) LD17.8(Vcc) U8.16(DIGIT_2)
DIGIT-2-4: LD23.3(Vcc) LD23.8(Vcc) U9.16(DIGIT_2)
DIGIT-3-3: LD16.3(Vcc) LD16.8(Vcc) U8.23(DIGIT_3)
DIGIT-3-4: LD22.3(Vcc) LD22.8(Vcc) U9.23(DIGIT_3)
DIGIT-4-3: LD15.3(Vcc) LD15.8(Vcc) U8.20(DIGIT_4)
DIGIT-4-4: LD21.3(Vcc) LD21.8(Vcc) U9.20(DIGIT_4)
DIGIT-5-3: LD14.3(Vcc) LD14.8(Vcc) U8.17(DIGIT_5)
DIGIT-5-4: LD20.3(Vcc) LD20.8(Vcc) U9.17(DIGIT_5)
DIGIT-6-3: LD13.3(Vcc) LD13.8(Vcc) U8.22(DIGIT_6)
DIGIT-6-4: LD19.3(Vcc) LD19.8(Vcc) U9.22(DIGIT_6)
ID-0-3: U8.12(ID0)
ID-0-4: U9.12(ID0)
ID-1-3: U8.11(ID1)
ID-1-4: U9.11(ID1)
ID-2-3: U8.13(ID2)
ID-2-4: U9.13(ID2)
ID-3-3: U8.14(ID3)
ID-3-4: U9.14(ID3)
ID-4-3: U8.10(ID4_(_/SHUTDOWN_))
ID-4-4: U9.10(ID4_(_/SHUTDOWN_))
ID-5-3: U8.6(ID5_(_/DECODE_))
ID-5-4: U9.6(ID5_(_/DECODE_))
ID-6-3: U8.5(ID6_(_HEX_/CODEB_))
ID-6-4: U9.5(ID6_(_HEX_/CODEB_))
ID-7-3: U8.7(ID7_(_DATA_COMING_))
ID-7-4: U9.7(ID7_(_DATA_COMING_))
LED-A-3: LD13.7(A) LD14.7(A) LD15.7(A) LD16.7(A) LD17.7(A) LD18.7(A) U8.27(Seg_A)
LED-A-4: LD19.7(A) LD20.7(A) LD21.7(A) LD22.7(A) LD23.7(A) LD24.7(A) U9.27(Seg_A)
LED-B-3: LD13.6(B) LD14.6(B) LD15.6(B) LD16.6(B) LD17.6(B) LD18.6(B) U8.3(Seg_B)
LED-B-4: LD19.6(B) LD20.6(B) LD21.6(B) LD22.6(B) LD23.6(B) LD24.6(B) U9.3(Seg_B)
LED-C-3: LD13.4(C) LD14.4(C) LD15.4(C) LD16.4(C) LD17.4(C) LD18.4(C) U8.1(Seg_C)
LED-C-4: LD19.4(C) LD20.4(C) LD21.4(C) LD22.4(C) LD23.4(C) LD24.4(C) U9.1(Seg_C)
LED-D-3: LD13.2(D) LD14.2(D) LD15.2(D) LD16.2(D) LD17.2(D) LD18.2(D) U8.25(Seg_D)
LED-D-4: LD19.2(D) LD20.2(D) LD21.2(D) LD22.2(D) LD23.2(D) LD24.2(D) U9.25(Seg_D)
LED-DP-3: LD13.5(DP) LD14.5(DP) LD15.5(DP) LD16.5(DP) LD17.5(DP) LD18.5(DP) U8.4(D.P.)
LED-DP-4: LD19.5(DP) LD20.5(DP) LD21.5(DP) LD22.5(DP) LD23.5(DP) LD24.5(DP) U9.4(D.P.)
LED-E-3: LD13.1(E) LD14.1(E) LD15.1(E) LD16.1(E) LD17.1(E) LD18.1(E) U8.2(Seg_E)
LED-E-4: LD19.1(E) LD20.1(E) LD21.1(E) LD22.1(E) LD23.1(E) LD24.1(E) U9.2(Seg_E)
LED-F-3: LD13.9(F) LD14.9(F) LD15.9(F) LD16.9(F) LD17.9(F) LD18.9(F) U8.24(Seg_F)
LED-F-4: LD19.9(F) LD20.9(F) LD21.9(F) LD22.9(F) LD23.9(F) LD24.9(F) U9.24(Seg_F)
LED-G-3: LD13.10(G) LD14.10(G) LD15.10(G) LD16.10(G) LD17.10(G) LD18.10(G) U8.26(Seg_G)
LED-G-4: LD19.10(G) LD20.10(G) LD21.10(G) LD22.10(G) LD23.10(G) LD24.10(G) U9.26(Seg_G)
MODE-3: U8.9(MODE)
MODE-4: U9.9(MODE)

Not connected (* = marked no-connect by the designer): U8 18(DIGIT_8) 21(DIGIT_7); U9 18(DIGIT_8) 21(DIGIT_7)

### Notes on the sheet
- D6
- D5
- D4
- D3
- D2
- D1
- 19.09.2010

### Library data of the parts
C8 C11 = 100NF_0805: as C12 on sheet PIC-1-2
C9 C10 = TR3 Tantal 47uF 16V: Tantal 47uF 16V
LD13-LD24 = SA52-11: 7-Segment-Anzeige 13mm

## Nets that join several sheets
GND: PIC-1-2 (50 pins), PIC-3-4 (50 pins), Display-1-2 (9 pins), Display-3-4 (6 pins)
VCC_5V: PIC-1-2 (24 pins), PIC-3-4 (25 pins), Display-1-2 (9 pins), Display-3-4 (6 pins)
/WRITE-1: PIC-1-2 (U10.20), Display-1-2 (U5.8)
/WRITE-2: PIC-1-2 (U11.20), Display-1-2 (U6.8)
/WRITE-3: PIC-3-4 (U12.20), Display-3-4 (U8.8)
/WRITE-4: PIC-3-4 (U13.20), Display-3-4 (U9.8)
ID-0-1: PIC-1-2 (U10.38), Display-1-2 (U5.12)
ID-0-2: PIC-1-2 (U11.38), Display-1-2 (U6.12)
ID-0-3: PIC-3-4 (U12.38), Display-3-4 (U8.12)
ID-0-4: PIC-3-4 (U13.38), Display-3-4 (U9.12)
ID-1-1: PIC-1-2 (U10.39), Display-1-2 (U5.11)
ID-1-2: PIC-1-2 (U11.39), Display-1-2 (U6.11)
ID-1-3: PIC-3-4 (U12.39), Display-3-4 (U8.11)
ID-1-4: PIC-3-4 (U13.39), Display-3-4 (U9.11)
ID-2-1: PIC-1-2 (U10.40), Display-1-2 (U5.13)
ID-2-2: PIC-1-2 (U11.40), Display-1-2 (U6.13)
ID-2-3: PIC-3-4 (U12.40), Display-3-4 (U8.13)
ID-2-4: PIC-3-4 (U13.40), Display-3-4 (U9.13)
ID-3-1: PIC-1-2 (U10.41), Display-1-2 (U5.14)
ID-3-2: PIC-1-2 (U11.41), Display-1-2 (U6.14)
ID-3-3: PIC-3-4 (U12.41), Display-3-4 (U8.14)
ID-3-4: PIC-3-4 (U13.41), Display-3-4 (U9.14)
ID-4-1: PIC-1-2 (U10.2), Display-1-2 (U5.10)
ID-4-2: PIC-1-2 (U11.2), Display-1-2 (U6.10)
ID-4-3: PIC-3-4 (U12.2), Display-3-4 (U8.10)
ID-4-4: PIC-3-4 (U13.2), Display-3-4 (U9.10)
ID-5-1: PIC-1-2 (U10.3), Display-1-2 (U5.6)
ID-5-2: PIC-1-2 (U11.3), Display-1-2 (U6.6)
ID-5-3: PIC-3-4 (U12.3), Display-3-4 (U8.6)
ID-5-4: PIC-3-4 (U13.3), Display-3-4 (U9.6)
ID-6-1: PIC-1-2 (U10.4), Display-1-2 (U5.5)
ID-6-2: PIC-1-2 (U11.4), Display-1-2 (U6.5)
ID-6-3: PIC-3-4 (U12.4), Display-3-4 (U8.5)
ID-6-4: PIC-3-4 (U13.4), Display-3-4 (U9.5)
ID-7-1: PIC-1-2 (U10.5), Display-1-2 (U5.7)
ID-7-2: PIC-1-2 (U11.5), Display-1-2 (U6.7)
ID-7-3: PIC-3-4 (U12.5), Display-3-4 (U8.7)
ID-7-4: PIC-3-4 (U13.5), Display-3-4 (U9.7)
MODE-1: PIC-1-2 (U10.19), Display-1-2 (U5.9)
MODE-2: PIC-1-2 (U11.19), Display-1-2 (U6.9)
MODE-3: PIC-3-4 (U12.19), Display-3-4 (U8.9)
MODE-4: PIC-3-4 (U13.19), Display-3-4 (U9.9)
